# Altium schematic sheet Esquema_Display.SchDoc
size A4
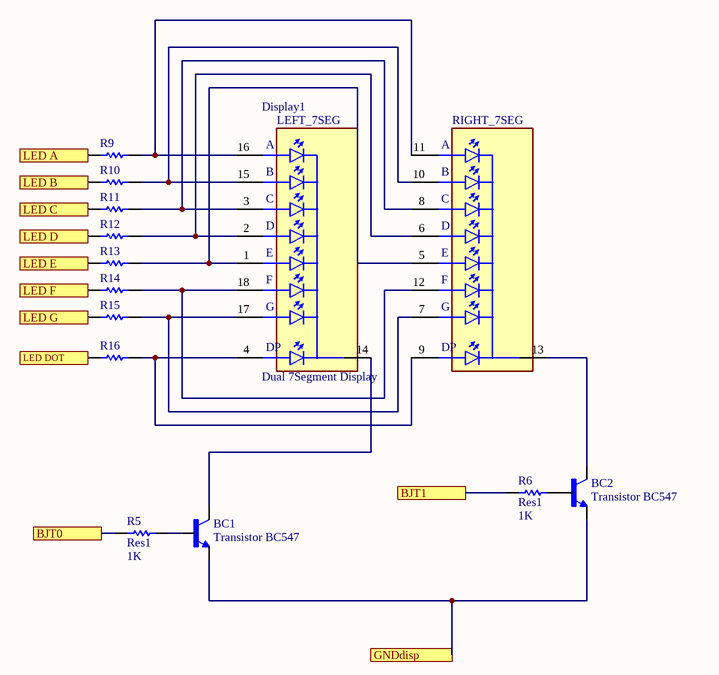
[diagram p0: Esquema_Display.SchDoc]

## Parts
BC1  Transistor BC547  [Transistor BC547]
BC2  Transistor BC547  [Transistor BC547]
Display1  Dual 7Segment Display  [Dual Digit Display]
R5  Res1  value 1K  [AXIAL-0.3]
R6  Res1  value 1K  [AXIAL-0.3]
R9  Res1  [AXIAL-0.3]  (value not drawn)
R10  Res1  [AXIAL-0.3]  (value not drawn)
R11  Res1  [AXIAL-0.3]  (value not drawn)
R12  Res1  [AXIAL-0.3]  (value not drawn)
R13  Res1  [AXIAL-0.3]  (value not drawn)
R14  Res1  [AXIAL-0.3]  (value not drawn)
R15  Res1  [AXIAL-0.3]  (value not drawn)
R16  Res1  [AXIAL-0.3]  (value not drawn)

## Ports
BJT0, BJT1, GNDdisp, LED A, LED B, LED C, LED D, LED DOT, LED E, LED F, LED G

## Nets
BJT0: R5.1 ; port BJT0
BJT1: R6.1 ; port BJT1
GNDdisp: BC1.1(E) BC2.1(E) ; port GNDdisp
LED A: R9.1 ; port LED A
LED B: R10.1 ; port LED B
LED C: R11.1 ; port LED C
LED D: R12.1 ; port LED D
LED DOT: R16.1 ; port LED DOT
LED E: R13.1 ; port LED E
LED F: R14.1 ; port LED F
LED G: R15.1 ; port LED G
NetBC1_2: BC1.2(B) R5.2
NetBC1_3: BC1.3(C) Display1.14(COM_1)
NetBC2_2: BC2.2(B) R6.2
NetBC2_3: BC2.3(C) Display1.13(COM_2)
NetDisplay1_1: Display1.1(E_1) Display1.5(E_2) R13.2
NetDisplay1_2: Display1.2(D_1) Display1.6(D_2) R12.2
NetDisplay1_3: Display1.3(C_1) Display1.8(C_2) R11.2
NetDisplay1_4: Display1.4(DP_1) Display1.9(DP_2) R16.2
NetDisplay1_7: Display1.7(G_2) Display1.17(G_1) R15.2
NetDisplay1_10: Display1.10(B_2) Display1.15(B_1) R10.2
NetDisplay1_11: Display1.11(A_2) Display1.16(A_1) R9.2
NetDisplay1_12: Display1.12(F_2) Display1.18(F_1) R14.2

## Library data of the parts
R5 R6 = Res1: Resistor
R9-R16 = Res1: Resistor; Value: 1K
